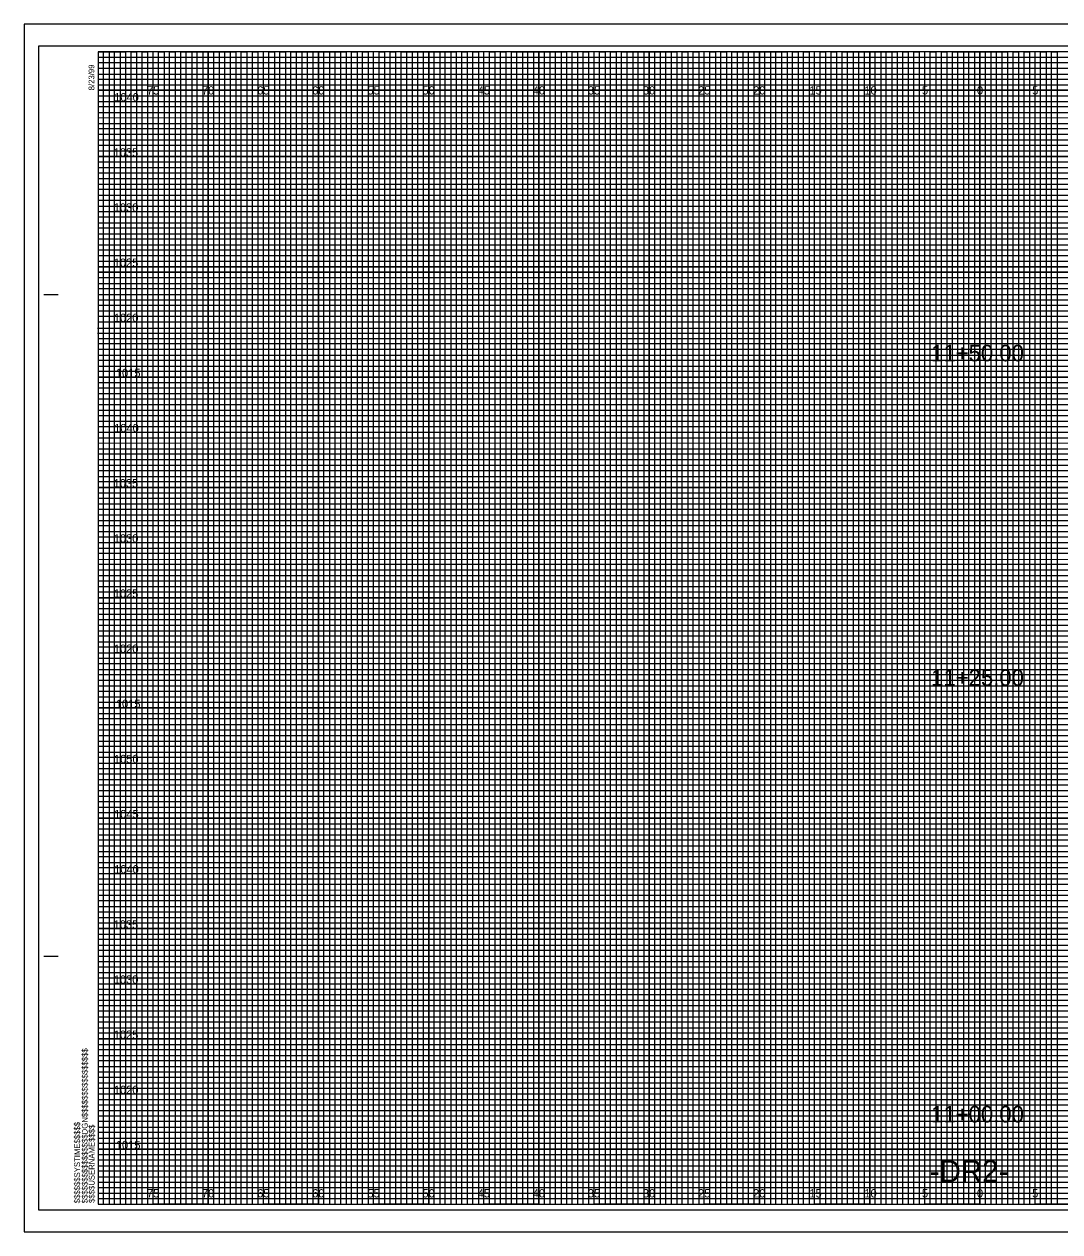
# Model space of a CAD drawing. Extents: x -7 to 182, y 218 to 327.
# Drawn here: x -6.7 to 87.2, y 217.5 to 327 of the extents above; entities that cross this region are included whole.
import ezdxf

# ---------------------------------------------------------------- set-up
doc = ezdxf.new("R2010")
doc.units = 0
for name, color, linetype in [('Exist Cross Section Cell', 7, 'Continuous'), ('Exist XS Center Line Elevation Label', 7, 'Continuous'), ('Exist XS Ground Line', 7, 'Continuous'), ('Prop CMT Concrete Structures', 7, 'Continuous'), ('Prop CMT DNC', 7, 'Continuous'), ('Prop CMT Guardrail Widen Shoulder', 7, 'Continuous'), ('Prop CMT Pvmt Course 1', 7, 'Continuous'), ('Prop CMT Pvmt Surface', 7, 'Continuous'), ('Prop CMT Shld Paved Course 1', 7, 'Continuous'), ('Prop CMT Slope Grass', 7, 'Continuous'), ('Prop CMT Subgrade Earthwork', 7, 'Continuous'), ('Prop XS Side Slope Text', 7, 'Continuous'), ('Typical Text Label CELL', 7, 'Continuous')]:
    doc.layers.add(name, color=color, linetype=linetype)

msp = doc.modelspace()

# ---------------------------------------------------------------- linework, layer by layer
at = {"layer": 'Exist XS Center Line Elevation Label'}
for points in [[(0, 324.5), (2.5, 324.5), (2.5, 220), (7.5, 220), (7.5, 324.5), (12.5, 324.5), (12.5, 220), (17.5, 220), (17.5, 324.5), (22.5, 324.5), (22.5, 220), (27.5, 220), (27.5, 324.5), (32.5, 324.5), (32.5, 220), (37.5, 220), (37.5, 324.5), (42.5, 324.5), (42.5, 220), (47.5, 220), (47.5, 324.5), (52.5, 324.5), (52.5, 220), (57.5, 220), (57.5, 324.5), (62.5, 324.5), (62.5, 220), (67.5, 220), (67.5, 324.5), (72.5, 324.5), (72.5, 220), (77.5, 220), (77.5, 324.5), (82.5, 324.5), (82.5, 220), (87.5, 220)], [(0, 322), (137.5, 322)], [(0, 312.5), (160, 312.5), (160, 317.5), (0, 317.5)], [(0, 302.5), (160, 302.5), (160, 307.5), (0, 307.5)], [(0, 292.5), (160, 292.5), (160, 297.5), (0, 297.5)], [(0, 282.5), (160, 282.5), (160, 287.5), (0, 287.5)], [(0, 272.5), (160, 272.5), (160, 277.5), (0, 277.5)], [(0, 262.5), (160, 262.5), (160, 267.5), (0, 267.5)], [(0, 252.5), (160, 252.5), (160, 257.5), (0, 257.5)], [(0, 242.5), (160, 242.5), (160, 247.5), (0, 247.5)], [(0, 232.5), (160, 232.5), (160, 237.5), (0, 237.5)], [(0, 222.5), (160, 222.5), (160, 227.5), (0, 227.5)]]:
    msp.add_lwpolyline(points, dxfattribs=at)
at = {"layer": 'Exist XS Ground Line'}
for p, q in [((5, 324.5), (0, 324.5)), ((5, 220), (5, 324.5)), ((15, 324.5), (10, 324.5)), ((10, 324.5), (10, 220)), ((15, 220), (15, 324.5)), ((25, 324.5), (20, 324.5)), ((20, 324.5), (20, 220)), ((25, 220), (25, 324.5)), ((35, 324.5), (30, 324.5)), ((30, 324.5), (30, 220)), ((35, 220), (35, 324.5)), ((45, 324.5), (40, 324.5)), ((40, 324.5), (40, 220)), ((45, 220), (45, 324.5)), ((55, 324.5), (50, 324.5)), ((50, 324.5), (50, 220)), ((55, 220), (55, 324.5)), ((65, 324.5), (60, 324.5)), ((60, 324.5), (60, 220)), ((65, 220), (65, 324.5)), ((75, 324.5), (70, 324.5)), ((70, 324.5), (70, 220)), ((75, 220), (75, 324.5)), ((85, 324.5), (80, 324.5)), ((80, 324.5), (80, 220)), ((85, 220), (85, 324.5)), ((10, 220), (5, 220)), ((20, 220), (15, 220)), ((30, 220), (25, 220)), ((40, 220), (35, 220)), ((50, 220), (45, 220)), ((60, 220), (55, 220)), ((70, 220), (65, 220)), ((80, 220), (75, 220)), ((90, 220), (85, 220))]:
    msp.add_line(p, q, dxfattribs=at)
for points in [[(0, 320), (160, 320), (160, 315), (0, 315)], [(0, 310), (160, 310), (160, 305), (0, 305)], [(0, 300), (160, 300), (160, 295), (0, 295)], [(0, 290), (160, 290), (160, 285), (0, 285)], [(0, 280), (160, 280), (160, 275), (0, 275)], [(0, 270), (160, 270), (160, 265), (0, 265)], [(0, 260), (160, 260), (160, 255), (0, 255)], [(0, 250), (160, 250), (160, 245), (0, 245)], [(0, 240), (160, 240), (160, 235), (0, 235)], [(0, 230), (160, 230), (160, 225), (0, 225)]]:
    msp.add_lwpolyline(points, dxfattribs=at)
at = {"layer": 'Prop CMT Concrete Structures'}
for p, q in [((5, 220), (5, 324.5)), ((10, 220), (10, 324.5)), ((15, 220), (15, 324.5)), ((20, 220), (20, 324.5)), ((25, 220), (25, 324.5)), ((30, 220), (30, 324.5)), ((35, 220), (35, 324.5)), ((40, 220), (40, 324.5)), ((45, 220), (45, 324.5)), ((50, 220), (50, 324.5)), ((55, 220), (55, 324.5)), ((60, 220), (60, 324.5)), ((65, 220), (65, 324.5)), ((70, 220), (70, 324.5)), ((75, 220), (75, 324.5)), ((80, 220), (80, 324.5)), ((85, 220), (85, 324.5)), ((0, 320), (160, 320)), ((0, 315), (160, 315)), ((0, 310), (160, 310)), ((0, 305), (160, 305)), ((0, 300), (160, 300)), ((0, 295), (160, 295)), ((0, 290), (160, 290)), ((0, 285), (160, 285)), ((0, 280), (160, 280)), ((0, 275), (160, 275)), ((0, 270), (160, 270)), ((0, 265), (160, 265)), ((0, 260), (160, 260)), ((0, 255), (160, 255)), ((0, 250), (160, 250)), ((0, 245), (160, 245)), ((0, 240), (160, 240)), ((0, 235), (160, 235)), ((0, 230), (160, 230)), ((0, 225), (160, 225))]:
    msp.add_line(p, q, dxfattribs=at)
at = {"layer": 'Prop CMT Guardrail Widen Shoulder'}
for p, q in [((161.65, 327), (-6.7, 327)), ((-6.7, 327), (-6.7, 217.5)), ((-6.7, 217.5), (161.65, 217.5))]:
    msp.add_line(p, q, dxfattribs=at)
at = {"layer": 'Prop CMT Pvmt Course 1'}
msp.add_lwpolyline([(-6.7, 217.5), (161.65, 217.5), (161.65, 327), (-6.7, 327)], close=True, dxfattribs=at)
at = {"layer": 'Prop CMT Pvmt Surface'}
for points in [[(0, 220), (0.5, 220), (0.5, 324.5), (1, 324.5), (1, 220)], [(1, 220), (1.5, 220), (1.5, 324.5), (2, 324.5), (2, 220)], [(2.5, 220), (3, 220), (3, 324.5), (3.5, 324.5), (3.5, 220)], [(3.5, 220), (4, 220), (4, 324.5), (4.5, 324.5), (4.5, 220)], [(5, 220), (5.5, 220), (5.5, 324.5), (6, 324.5), (6, 220)], [(6, 220), (6.5, 220), (6.5, 324.5), (7, 324.5), (7, 220)], [(7.5, 220), (8, 220), (8, 324.5), (8.5, 324.5), (8.5, 220)], [(8.5, 220), (9, 220), (9, 324.5), (9.5, 324.5), (9.5, 220)], [(10, 220), (10.5, 220), (10.5, 324.5), (11, 324.5), (11, 220)], [(11, 220), (11.5, 220), (11.5, 324.5), (12, 324.5), (12, 220)], [(12.5, 220), (13, 220), (13, 324.5), (13.5, 324.5), (13.5, 220)], [(13.5, 220), (14, 220), (14, 324.5), (14.5, 324.5), (14.5, 220)], [(15, 220), (15.5, 220), (15.5, 324.5), (16, 324.5), (16, 220)], [(16, 220), (16.5, 220), (16.5, 324.5), (17, 324.5), (17, 220)], [(17.5, 220), (18, 220), (18, 324.5), (18.5, 324.5), (18.5, 220)], [(18.5, 220), (19, 220), (19, 324.5), (19.5, 324.5), (19.5, 220)], [(20, 220), (20.5, 220), (20.5, 324.5), (21, 324.5), (21, 220)], [(21, 220), (21.5, 220), (21.5, 324.5), (22, 324.5), (22, 220)], [(22.5, 220), (23, 220), (23, 324.5), (23.5, 324.5), (23.5, 220)], [(23.5, 220), (24, 220), (24, 324.5), (24.5, 324.5), (24.5, 220)], [(25, 220), (25.5, 220), (25.5, 324.5), (26, 324.5), (26, 220)], [(26, 220), (26.5, 220), (26.5, 324.5), (27, 324.5), (27, 220)], [(27.5, 220), (28, 220), (28, 324.5), (28.5, 324.5), (28.5, 220)], [(28.5, 220), (29, 220), (29, 324.5), (29.5, 324.5), (29.5, 220)], [(30, 220), (30.5, 220), (30.5, 324.5), (31, 324.5), (31, 220)], [(31, 220), (31.5, 220), (31.5, 324.5), (32, 324.5), (32, 220)], [(32.5, 220), (33, 220), (33, 324.5), (33.5, 324.5), (33.5, 220)], [(33.5, 220), (34, 220), (34, 324.5), (34.5, 324.5), (34.5, 220)], [(35, 220), (35.5, 220), (35.5, 324.5), (36, 324.5), (36, 220)], [(36, 220), (36.5, 220), (36.5, 324.5), (37, 324.5), (37, 220)], [(37.5, 220), (38, 220), (38, 324.5), (38.5, 324.5), (38.5, 220)], [(38.5, 220), (39, 220), (39, 324.5), (39.5, 324.5), (39.5, 220)], [(40, 220), (40.5, 220), (40.5, 324.5), (41, 324.5), (41, 220)], [(41, 220), (41.5, 220), (41.5, 324.5), (42, 324.5), (42, 220)], [(42.5, 220), (43, 220), (43, 324.5), (43.5, 324.5), (43.5, 220)], [(43.5, 220), (44, 220), (44, 324.5), (44.5, 324.5), (44.5, 220)], [(45, 220), (45.5, 220), (45.5, 324.5), (46, 324.5), (46, 220)], [(46, 220), (46.5, 220), (46.5, 324.5), (47, 324.5), (47, 220)], [(47.5, 220), (48, 220), (48, 324.5), (48.5, 324.5), (48.5, 220)], [(48.5, 220), (49, 220), (49, 324.5), (49.5, 324.5), (49.5, 220)], [(50, 220), (50.5, 220), (50.5, 324.5), (51, 324.5), (51, 220)], [(51, 220), (51.5, 220), (51.5, 324.5), (52, 324.5), (52, 220)], [(52.5, 220), (53, 220), (53, 324.5), (53.5, 324.5), (53.5, 220)], [(53.5, 220), (54, 220), (54, 324.5), (54.5, 324.5), (54.5, 220)], [(55, 220), (55.5, 220), (55.5, 324.5), (56, 324.5), (56, 220)], [(56, 220), (56.5, 220), (56.5, 324.5), (57, 324.5), (57, 220)], [(57.5, 220), (58, 220), (58, 324.5), (58.5, 324.5), (58.5, 220)], [(58.5, 220), (59, 220), (59, 324.5), (59.5, 324.5), (59.5, 220)], [(60, 220), (60.5, 220), (60.5, 324.5), (61, 324.5), (61, 220)], [(61, 220), (61.5, 220), (61.5, 324.5), (62, 324.5), (62, 220)], [(62.5, 220), (63, 220), (63, 324.5), (63.5, 324.5), (63.5, 220)], [(63.5, 220), (64, 220), (64, 324.5), (64.5, 324.5), (64.5, 220)], [(65, 220), (65.5, 220), (65.5, 324.5), (66, 324.5), (66, 220)], [(66, 220), (66.5, 220), (66.5, 324.5), (67, 324.5), (67, 220)], [(67.5, 220), (68, 220), (68, 324.5), (68.5, 324.5), (68.5, 220)], [(68.5, 220), (69, 220), (69, 324.5), (69.5, 324.5), (69.5, 220)], [(70, 220), (70.5, 220), (70.5, 324.5), (71, 324.5), (71, 220)], [(71, 220), (71.5, 220), (71.5, 324.5), (72, 324.5), (72, 220)], [(72.5, 220), (73, 220), (73, 324.5), (73.5, 324.5), (73.5, 220)], [(73.5, 220), (74, 220), (74, 324.5), (74.5, 324.5), (74.5, 220)], [(75, 220), (75.5, 220), (75.5, 324.5), (76, 324.5), (76, 220)], [(76, 220), (76.5, 220), (76.5, 324.5), (77, 324.5), (77, 220)], [(77.5, 220), (78, 220), (78, 324.5), (78.5, 324.5), (78.5, 220)], [(78.5, 220), (79, 220), (79, 324.5), (79.5, 324.5), (79.5, 220)], [(80, 220), (80.5, 220), (80.5, 324.5), (81, 324.5), (81, 220)], [(81, 220), (81.5, 220), (81.5, 324.5), (82, 324.5), (82, 220)], [(82.5, 220), (83, 220), (83, 324.5), (83.5, 324.5), (83.5, 220)], [(83.5, 220), (84, 220), (84, 324.5), (84.5, 324.5), (84.5, 220)], [(85, 220), (85.5, 220), (85.5, 324.5), (86, 324.5), (86, 220)], [(86, 220), (86.5, 220), (86.5, 324.5), (87, 324.5), (87, 220)]]:
    msp.add_lwpolyline(points, dxfattribs=at)
at = {"layer": 'Prop CMT Shld Paved Course 1'}
for p, q in [((0, 324), (130, 324)), ((130, 323.49), (0, 323.49)), ((0, 323.49), (0, 323)), ((0, 323), (130, 323)), ((130, 322.44), (0, 322.44)), ((0, 322.44), (0, 321.5)), ((0, 321.5), (160, 321.5))]:
    msp.add_line(p, q, dxfattribs=at)
for points in [[(0, 321), (135, 321), (160, 321), (160, 321), (0, 321)], [(0, 320.5), (160, 320.5), (160, 319.5), (0, 319.5)], [(0, 319), (160, 319), (160, 318.5), (0, 318.49)], [(0, 318), (160, 318), (160, 317), (0, 317)], [(0, 316.5), (160, 316.5), (160, 316), (0, 316)], [(0, 315.5), (160, 315.5), (160, 314.5), (0, 314.5)], [(0, 314), (160, 314), (160, 313.5), (0, 313.5)], [(0, 313), (160, 313), (160, 312), (0, 312)], [(0, 311.5), (160, 311.5), (160, 311), (0, 311)], [(0, 310.5), (160, 310.5), (160, 309.5), (0, 309.5)], [(0, 309), (160, 309), (160, 308.5), (0, 308.5)], [(0, 308), (160, 308), (160, 306.98), (160, 306.5), (160, 306), (0, 306)], [(0, 307), (160, 307), (160, 306.5), (0, 306.5)], [(0, 305.5), (160, 305.5), (160, 304.5), (0, 304.51)], [(0, 304.51), (160, 304.5), (160, 304), (0, 304)], [(0, 303.5), (160, 303.5), (160, 303), (0, 303)], [(0, 302), (160, 302), (160, 301.5), (0, 301.5)], [(0, 301), (160, 301), (160, 300.5), (0, 300.5)], [(-0.04, 299.44), (160, 299.44), (160, 298.94), (-0.04, 298.94)], [(0, 298.5), (160, 298.5), (160, 298), (0, 298)], [(0, 297), (160, 297), (160, 296.5), (0, 296.5)], [(0, 296), (160, 296), (160, 295.5), (0, 295.5)], [(0, 294.5), (160, 294.5), (160, 294), (0, 294)], [(0, 293.5), (160, 293.5), (160, 293), (0, 293)], [(0, 292), (160, 292), (160, 291.5), (0, 291.5)], [(0, 291), (160, 291), (160, 290.5), (0, 290.5)], [(0, 289.5), (160, 289.5), (160, 288.99), (0, 289)], [(0, 288.5), (160, 288.5), (160, 288), (0, 288)], [(0, 287), (160, 287), (160, 286.5), (0, 286.5)], [(0, 286), (160, 286), (160, 285.5), (0, 285.5)], [(0, 284.5), (160, 284.5), (160, 284), (0, 284)], [(0, 283.5), (160, 283.5), (160, 283), (0, 283)], [(0, 282), (160, 282), (160, 281.5), (0, 281.5)], [(0, 281), (160, 281), (160, 280.5), (0, 280.5)], [(0, 279.5), (160, 279.5), (160, 279), (0, 279)], [(0, 278.5), (160.03, 278.45), (160, 278), (0, 278)], [(0, 277), (160, 277), (160, 276.5), (0, 276.5)], [(0, 276), (160, 276), (160, 275.5), (0, 275.5)], [(0, 274.5), (160, 274.5), (160, 274), (0, 274)], [(0, 273.5), (160, 273.5), (160, 273), (0, 273)], [(0, 272), (160, 272), (160, 271.5), (0, 271.5)], [(0, 271), (160, 271), (160, 270.5), (0, 270.5)], [(0, 269.5), (160, 269.5), (160, 269), (0, 269)], [(0, 268.5), (160, 268.5), (160, 268), (0, 268)], [(0, 267), (160, 267), (160, 266.5), (0, 266.5)], [(0, 266), (160, 266), (160, 265.5), (0, 265.5)], [(0, 264.5), (160, 264.5), (160, 264), (0, 264)], [(0, 263.5), (160, 263.5), (160, 263), (0, 263)], [(0, 262), (160, 262), (160, 261.5), (0, 261.5)], [(0, 261), (160, 261), (160, 260.5), (0, 260.5)], [(0, 259.5), (160, 259.5), (160, 258.99), (0, 259)], [(0, 258.5), (160, 258.5), (160, 258), (0, 258)], [(0, 257), (160, 257), (160, 256.5), (0, 256.5)], [(0, 256), (160, 256), (160, 255.5), (0, 255.5)], [(0, 254.5), (160, 254.5), (160, 254), (0, 254)], [(0, 253.5), (160, 253.5), (160, 253), (0, 253)], [(0, 252), (160, 252), (160, 251.5), (0, 251.5)], [(0, 251), (160, 251), (160, 250.5), (0, 250.5)], [(0, 249.5), (160, 249.5), (160, 249), (0, 249)], [(0, 248.5), (160.03, 248.46), (160, 248), (0, 248)], [(0, 247), (160, 247), (160, 246.5), (0, 246.5)], [(0, 246), (160, 246), (160, 245.5), (0, 245.5)], [(0, 244.5), (160, 244.5), (160, 244), (0, 244)], [(0, 243.5), (160, 243.5), (160, 243), (0, 243)], [(0, 242), (160, 242), (160, 241.5), (0, 241.5)], [(0, 241), (160, 241), (160, 240.5), (0, 240.5)], [(0, 239.5), (160, 239.5), (160, 239), (0, 239)], [(0, 238.5), (160, 238.5), (160, 238), (0, 238)], [(0, 237), (160, 237), (160, 236.5), (0, 236.5)], [(0, 236), (160, 236), (160, 235.5), (0, 235.5)], [(0, 234.5), (160, 234.5), (160, 234), (0, 234)], [(0, 233.5), (160, 233.5), (160, 233), (0, 233)], [(0, 232), (160, 232), (160, 231.5), (0, 231.5)], [(0, 231), (160, 231), (160, 230.5), (0, 230.5)], [(0, 229.5), (160, 229.5), (160, 229), (0, 229)], [(0, 228.5), (160, 228.5), (160, 228), (0, 228)], [(0, 227), (160, 227), (160, 226.5), (0, 226.5)], [(0, 226), (160, 226), (160, 225.5), (0, 225.5)], [(0, 224.5), (160, 224.5), (160, 224), (0, 224)], [(0, 223.5), (160, 223.5), (160, 223), (0, 223)], [(0, 222), (160, 222), (160, 221.5), (0, 221.5)], [(0, 221), (160, 221), (160, 220.5), (0, 220.5)]]:
    msp.add_lwpolyline(points, dxfattribs=at)
at = {"layer": 'Prop CMT Slope Grass'}
msp.add_lwpolyline([(-5.4, 219.5), (161.2, 219.5), (161.2, 325), (-5.4, 325)], close=True, dxfattribs=at)
at = {"layer": 'Prop CMT Subgrade Earthwork'}
for p, q in [((-4.9, 302.5), (-3.65, 302.5)), ((-4.85, 302.5), (-3.6, 302.5)), ((-4.9, 242.5), (-3.65, 242.5)), ((-4.85, 242.5), (-3.6, 242.5)), ((0, 220), (0, 220)), ((0, 220), (0, 220)), ((0, 220), (0, 220)), ((0, 220), (0, 220)), ((0, 220), (0, 220)), ((0, 220), (0, 220)), ((0, 220), (0, 220))]:
    msp.add_line(p, q, dxfattribs=at)
msp.add_lwpolyline([(160, 324.5), (0, 324.5), (0, 220), (160, 220)], close=True, dxfattribs=at)

# ---------------------------------------------------------------- texts
at = {"layer": 'Exist Cross Section Cell'}
for s, p in [('75', (4.44, 320.62)), ('70', (9.43, 320.62)), ('65', (14.44, 320.62)), ('60', (19.43, 320.62)), ('55', (24.44, 320.62)), ('50', (29.43, 320.62)), ('45', (34.44, 320.62)), ('40', (39.43, 320.62)), ('35', (44.44, 320.62)), ('30', (49.43, 320.62)), ('25', (54.44, 320.62)), ('20', (59.43, 320.62)), ('15', (64.53, 320.62)), ('10', (69.52, 320.62)), ('5', (74.74, 320.62)), ('0', (79.73, 320.62)), ('0', (79.73, 320.62)), ('5', (84.74, 320.62)), ('75', (4.44, 220.62)), ('70', (9.43, 220.62)), ('65', (14.44, 220.62)), ('60', (19.43, 220.62)), ('55', (24.44, 220.62)), ('50', (29.43, 220.62)), ('45', (34.44, 220.62)), ('40', (39.43, 220.62)), ('35', (44.44, 220.62)), ('30', (49.43, 220.62)), ('25', (54.44, 220.62)), ('20', (59.43, 220.62)), ('15', (64.53, 220.62)), ('10', (69.52, 220.62)), ('5', (74.74, 220.62)), ('0', (79.73, 220.62)), ('0', (79.73, 220.62)), ('5', (84.74, 220.62))]:
    msp.add_text(s, height=0.75, dxfattribs=at).set_placement(p)
at = {"layer": 'Prop CMT DNC'}
msp.add_text('-DR2-', height=2, dxfattribs=at).set_placement((75.45, 222))
at = {"layer": 'Prop CMT Subgrade Earthwork'}
for s, p in [('8/23/99', (-0.33, 321)), ('$$$$$$$$$$$$$$$$DGN$$$$$$$$$$$$$$$$', (-0.94, 220.09)), ('$$$$$$SYSTIME$$$$$', (-1.63, 220.09)), ('$$$$USERNAME$$$$', (-0.31, 220.12))]:
    msp.add_text(s, height=0.525, rotation=90, dxfattribs=at).set_placement(p)
at = {"layer": 'Prop XS Side Slope Text'}
for s, p in [('11+50.00', (75.57, 296.43)), ('11+25.00', (75.57, 267)), ('11+00.00', (75.57, 227.42))]:
    msp.add_text(s, height=1.5, dxfattribs=at).set_placement(p)
at = {"layer": 'Typical Text Label CELL'}
for s, p in [('1040', (1.47, 320)), ('1035', (1.42, 315)), ('1030', (1.43, 310)), ('1025', (1.43, 305)), ('1020', (1.44, 300)), ('1015', (1.62, 295)), ('1040', (1.47, 290)), ('1035', (1.42, 285)), ('1030', (1.43, 280)), ('1025', (1.43, 275)), ('1020', (1.44, 270)), ('1015', (1.62, 265)), ('1050', (1.45, 260)), ('1045', (1.46, 255)), ('1040', (1.47, 250)), ('1035', (1.42, 245)), ('1030', (1.43, 240)), ('1025', (1.43, 235)), ('1020', (1.44, 230)), ('1015', (1.62, 225))]:
    msp.add_text(s, height=0.75, dxfattribs=at).set_placement(p)

doc.saveas('drawing.dxf')
